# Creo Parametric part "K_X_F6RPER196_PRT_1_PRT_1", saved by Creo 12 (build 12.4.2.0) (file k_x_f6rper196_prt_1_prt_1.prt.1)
Units: Custom; MM, KILOGRAM, SECS

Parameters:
  PTC_WM_ITERATION = "0"
  PTC_WM_VERSION = "-.0"
  PTC_WM_LIFECYCLE_STATE = "In Work"
  PTC_WM_LIFECYCLE = "MO_CADDocument"
  PTC_WM_CREATED_BY = "Maximilian Roepper (Z0017RMS: MO)"
  PTC_WM_CREATED_ON = "18-Sep-26 11:36:42 AM"
  PTC_WM_MODIFIED_BY = "Maximilian Roepper (Z0017RMS: MO)"
  PTC_WM_MODIFIED_ON = "18-Sep-26 11:36:46 AM"
  PDMLINKNUMBER = "PDM000071455147"
  PTC_WM_NAME = "k_x_f6rper196_prt_1_prt_1.prt"
  PTC_WM_NUMBER = "PDM000071455147"

Other parameters: WEIGHT, WEIGHT_FACTOR, WEIGHT_ADD, _MASS_TEMP, _DIFF_TEMP, MC_ERRORS, SUPPLIER

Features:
  1. coordinate system
  2. datum plane "PRT_YZ"
  3. datum plane "PRT_XY"
  4. datum plane "PRT_XZ"
  5. coordinate system
  6. datum axis
  7. datum axis
  8. datum axis
  9. coordinate system
  10. imported feature
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
Other named items: PRT, SIEMENS_MO, DRW_VIEW_ORG, PRT_X, PRT_Y, PRT_Z, CS0, ROUGH_GROB

Layers: 00_STD_CSYS-KSYS, 01_STD_PLANES-EBENEN, 02_STD_AXES-ACHSEN, 03_STD_CSYS-KSYS, 24_IMPORT_FEAT-IMPORT_KE

Surfaces: 14 plane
